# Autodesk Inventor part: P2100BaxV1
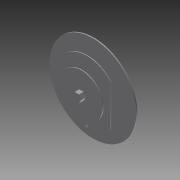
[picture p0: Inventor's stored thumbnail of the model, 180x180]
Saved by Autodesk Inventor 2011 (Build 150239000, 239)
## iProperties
Created: 2014-07
Part Number: P2100BaxV1
Document SubType Name: Modeling
Designer: Evgeny
Density: 1 g/cm^3
Author: Evgeny
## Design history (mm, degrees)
sketch "Эскиз1"
  geometry: L1 (31, 26.833)-(31, -26.833); L2 (-31, -26.833)-(-31, 26.833); C1 r 1.35 at (0, -39); A1 r 41 centre (0, 0) between (31, 26.833) and (-31, 26.833); A2 r 41 centre (0, 0) between (-31, -26.833) and (31, -26.833); 1 further point
  constraints: 4 end point, 4 point on circle, 3 centre point, 1 coincident, 1 parallel
  dimensions: "d1" = 62 distance between parallel lines of L1 L2; "d2" = 31 distance from line of L2 point (0, 0); "d3" = 41 radius of A1; "d4" = 41 radius of A2; "d7" = 2.7 diameter of C1; "d8" = 0 horizontal distance of point (0, 0) C1.centre; "d9" = 39 distance of point (0, 0) C1.centre
extrude "Выдавливание1" new body sketch "Эскиз1" distance "d10" = 1; taper "d11" = 0 deg
sketch "Эскиз2"
  geometry: C1 r 4 at (0, 0); A1 r 41 centre (0, 0) between (31, 26.833) and (-31, 26.833) reference
  constraints: 1 centre point, 1 coincident
  dimensions: "d12" = 8 diameter of C1
extrude "Выдавливание2" join sketch "Эскиз2" distance "d13" = 6; taper "d14" = 0 deg
sketch "Эскиз3"
  geometry: C1 r 4 at (0, 0) reference; C2 r 28 at (0, 0)
  constraints: 1 centre point, 1 coincident
  dimensions: "d15" = 56 diameter of C2
extrude "Выдавливание3" join sketch "Эскиз3" distance "d16" = 1; taper "d17" = 0 deg
sketch "Эскиз4"
  geometry: L1 (5.774, 0)-(2.887, -5); L2 (2.887, -5)-(-2.887, -5); L3 (-2.887, -5)-(-5.774, 0); L4 (-5.774, 0)-(-2.887, 5); L5 (-2.887, 5)-(2.887, 5); L6 (2.887, 5)-(5.774, 0); C1 r 28 at (0, 0) reference; 1 further point
  constraints: 12 end point, 1 coincident, 13 other
  dimensions: "d18" = 10 distance between parallel lines of L2 L5
extrude "Выдавливание4" join sketch "Эскиз4" distance "d19" = 6; taper "d20" = 0 deg
sketch "Эскиз5"
  geometry: C1 r 4 at (0, 0); A1 r 41 centre (0, 0) between (31, 26.833) and (-31, 26.833) reference
  constraints: 1 centre point, 1 coincident
  dimensions: "d21" = 8 diameter of C1
extrude "Выдавливание5" join sketch "Эскиз5" distance "d22" = 7; taper "d23" = 0 deg
sketch "Эскиз6"
  geometry: C1 r 4 at (0, 0) reference; C2 r 56.75 at (0, 0); C3 r 4 at (0, -39)
  constraints: 2 centre point, 1 coincident
  dimensions: "d24" = 113.5 diameter of C2; "d33" = 8 diameter of C3; "d50" = 39 distance of C3.centre C1.centre
extrude "Выдавливание11" join sketch "Эскиз6" distance "d38" = 1.5; taper "d39" = 0 deg
sketch "Эскиз9"
  geometry: L1 (5.774, 0)-(2.887, -5); L2 (2.887, -5)-(-2.887, -5); L3 (-2.887, -5)-(-5.774, 0); L4 (-5.774, 0)-(-2.887, 5); L5 (-2.887, 5)-(2.887, 5); L6 (2.887, 5)-(5.774, 0); C1 r 56.75 at (0, 0) reference; 1 further point
  constraints: 12 end point, 1 coincident, 13 other
  dimensions: "d40" = 10 distance between parallel lines of L2 L5
extrude "Выдавливание12" join sketch "Эскиз9" distance "d41" = 6; taper "d42" = 0 deg
sketch "Эскиз10"
  geometry: C1 r 3 at (0, 0); 1 further point
  constraints: 1 centre point, 1 coincident
  dimensions: "d43" = 6 diameter of C1
extrude "Выдавливание13" join sketch "Эскиз10" distance "d44" = 6; taper "d45" = 0 deg
extrude "Выдавливание14" join sketch "Эскиз1" distance "d46" = 2; taper "d48" = 0 deg; dims "d47" = 8.5, "d49" = 0
node "Твердое тело1"
other parameters: "d0" = 82
